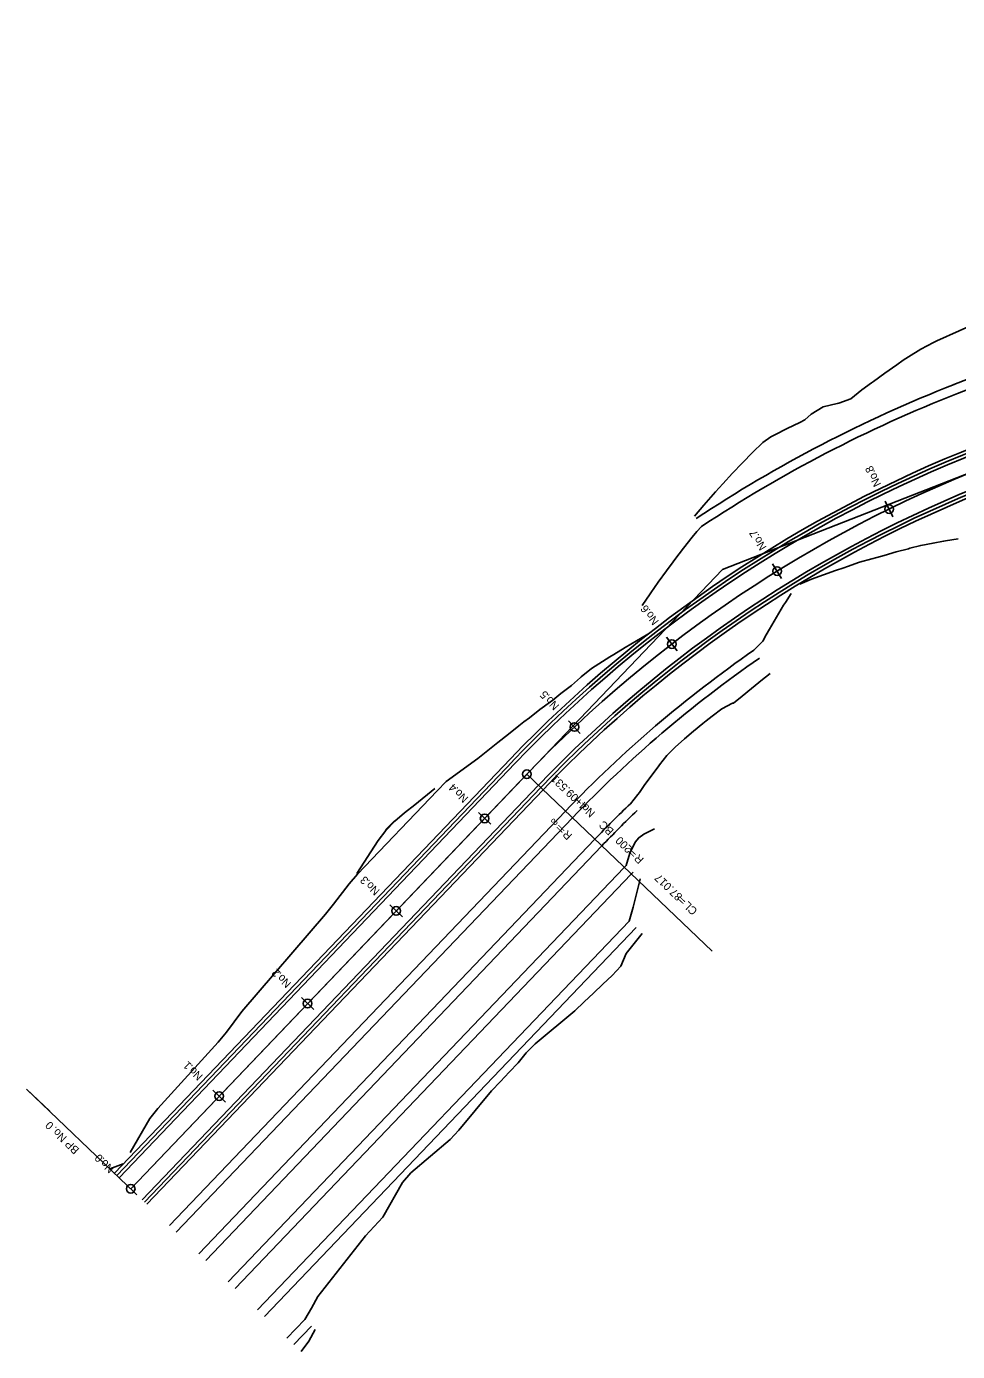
# Model space of a CAD drawing. Extents: x 46571 to 46965, y 10697 to 11034.
# Drawn here: x 46571.1 to 46716.5, y 10697.1 to 10904 of the extents above; entities that cross this region are included whole.
import ezdxf

# ---------------------------------------------------------------- set-up
doc = ezdxf.new("R2010")
doc.units = 0
for name, color, linetype in [('Default', 7, 'Continuous'), ('作業レイヤ1', 7, 'Continuous'), ('地形_主曲線_等高線', 7, 'Continuous'), ('地形_土崖 コンクリート、堅固な石積等斜面（地理院地図Vector）', 7, 'Continuous'), ('建物_普通建物_普通建物（地理院地図Vector）', 7, 'Continuous'), ('建物_普通建物_普通建物（外周線）（地理院地図Vector）', 7, 'Continuous'), ('河川_通常部（地理院地図Vector）', 7, 'Continuous'), ('現況_地形_三角形', 7, 'Continuous'), ('等高線等深線_等高線_主曲線通常部（地理院地図Vector）', 7, 'Continuous'), ('道路_通常部_通常部（地理院地図Vector）', 7, 'Continuous')]:
    doc.layers.add(name, color=color, linetype=linetype)

msp = doc.modelspace()

# ---------------------------------------------------------------- linework, layer by layer
at = {"layer": 'Default'}
for p, q in [((46679.76, 10819.21), (46896.47, 10904.04)), ((46705.79, 10828.67), (46705.79, 10828.67)), ((46587.37, 10722.52), (46679.76, 10819.21)), ((46688.3, 10818.98), (46688.3, 10818.98)), ((46671.86, 10807.59), (46671.86, 10807.59)), ((46656.65, 10794.63), (46656.65, 10794.63)), ((46587.37, 10722.52), (46649.22, 10787.25)), ((46649.22, 10787.25), (46649.22, 10787.25)), ((46649.22, 10787.25), (46678.14, 10759.62)), ((46642.64, 10780.36), (46642.64, 10780.36)), ((46628.82, 10765.9), (46628.82, 10765.9)), ((46615, 10751.44), (46615, 10751.44)), ((46586.88, 10722.98), (46571.1, 10738.06)), ((46571.1, 10738.06), (46574.72, 10734.61)), ((46601.19, 10736.98), (46601.19, 10736.98)), ((46587.37, 10722.52), (46587.37, 10722.52)), ((46587.37, 10722.52), (46587.37, 10722.52))]:
    msp.add_line(p, q, dxfattribs=at)
for centre in [(46705.79, 10828.67), (46688.3, 10818.98), (46671.86, 10807.59), (46656.65, 10794.63), (46649.22, 10787.25), (46642.64, 10780.36), (46628.82, 10765.9), (46615, 10751.44), (46601.19, 10736.98), (46587.37, 10722.52), (46587.37, 10722.52)]:
    msp.add_circle(centre, 0.675, dxfattribs=at)
msp.add_arc((46793.83, 10649.09), 200, 111.3768, 136.3054, dxfattribs=at)
msp.add_arc((46793.83, 10649.09), 200, 111.3768, 136.3054, dxfattribs=at)
at = {"layer": '作業レイヤ1'}
msp.add_line((46587.37, 10722.52), (46649.22, 10787.25), dxfattribs=at)
msp.add_arc((46793.83, 10649.09), 200, 111.3768, 136.3054, dxfattribs=at)
at = {"layer": '地形_主曲線_等高線'}
for p, q in [((46715.92, 10848.11), (46760.11, 10865.41)), ((46716.47, 10846.72), (46760.66, 10864.01)), ((46584.13, 10725.61), (46586.2, 10726.4))]:
    msp.add_line(p, q, dxfattribs=at)
for points in [[(46675.41, 10827.55), (46676.85, 10829.26), (46678.32, 10830.95), (46678.68, 10831.35), (46679.82, 10832.62), (46681.35, 10834.27), (46682.83, 10835.83), (46682.9, 10835.9), (46684.48, 10837.51), (46686.09, 10839.09), (46687.31, 10839.93), (46687.94, 10840.26), (46689.89, 10841.24), (46691.86, 10842.19), (46692.62, 10842.6), (46693.64, 10843.5), (46695.52, 10844.63), (46697.7, 10845.15), (46697.95, 10845.21), (46699.79, 10845.86), (46701.53, 10847.27), (46703.03, 10848.38), (46703.33, 10848.6), (46705.15, 10849.9), (46706.99, 10851.19), (46708.01, 10851.9), (46708.84, 10852.46), (46710.73, 10853.65), (46712.7, 10854.69), (46713.25, 10854.95), (46723.72, 10859.62)], [(46667.24, 10813.6), (46668.47, 10815.42), (46668.57, 10815.57), (46669.73, 10817.23), (46671.01, 10819.01), (46672.06, 10820.43), (46672.33, 10820.79), (46673.67, 10822.54), (46675.04, 10824.28), (46675.76, 10825.17), (46676.49, 10825.93)], [(46691.87, 10816.95), (46693.7, 10817.71), (46695.57, 10818.4), (46697.44, 10819.07), (46698.71, 10819.51), (46699.31, 10819.72), (46701.19, 10820.36), (46703.1, 10820.91), (46703.86, 10821.12), (46705.01, 10821.44), (46706.91, 10821.97), (46708.82, 10822.48), (46709.04, 10822.54), (46710.72, 10822.99), (46712.67, 10823.36), (46714.3, 10823.65), (46714.62, 10823.71), (46716.57, 10824.04)]]:
    msp.add_lwpolyline(points, dxfattribs=at)
for radius in [213.73, 212.23]:
    msp.add_arc((46793.83, 10649.09), radius, 111.3768, 123.5659, dxfattribs=at)
at = {"layer": '地形_土崖 コンクリート、堅固な石積等斜面（地理院地図Vector）'}
for p, q in [((46585.2, 10724.59), (46647.05, 10789.32)), ((46589.54, 10720.44), (46651.39, 10785.18))]:
    msp.add_line(p, q, dxfattribs=at)
for radius in [203, 197]:
    msp.add_arc((46793.83, 10649.09), radius, 111.3768, 136.3054, dxfattribs=at)
at = {"layer": '建物_普通建物_普通建物（地理院地図Vector）'}
for p, q in [((46585.56, 10724.24), (46647.41, 10788.98)), ((46589.18, 10720.79), (46651.03, 10785.52))]:
    msp.add_line(p, q, dxfattribs=at)
for radius in [202.5, 197.5]:
    msp.add_arc((46793.83, 10649.09), radius, 111.3768, 136.3054, dxfattribs=at)
at = {"layer": '建物_普通建物_普通建物（外周線）（地理院地図Vector）'}
for p, q in [((46584.84, 10724.93), (46646.69, 10789.67)), ((46589.9, 10720.1), (46651.75, 10784.83))]:
    msp.add_line(p, q, dxfattribs=at)
for radius in [203.5, 196.5]:
    msp.add_arc((46793.83, 10649.09), radius, 111.3768, 136.3054, dxfattribs=at)
at = {"layer": '現況_地形_三角形'}
for p, q in [((46593.41, 10716.75), (46655.26, 10781.48)), ((46594.49, 10715.71), (46656.34, 10780.45)), ((46627.15, 10778.56), (46628.54, 10780)), ((46598, 10712.36), (46659.85, 10777.09)), ((46599.09, 10711.33), (46660.93, 10776.06)), ((46608.27, 10702.55), (46666.3, 10763.29)), ((46612.86, 10698.17), (46615.62, 10701.06))]:
    msp.add_line(p, q, dxfattribs=at)
for points in [[(46684.69, 10806.63), (46686.07, 10808.02), (46686.6, 10809.01), (46687.11, 10809.92), (46688.19, 10811.8), (46689.31, 10813.65), (46689.59, 10814.09), (46690.48, 10815.47)], [(46587.27, 10728.15), (46590.37, 10733.48), (46591.6, 10735.07), (46601.03, 10745.43), (46602.33, 10746.95), (46603.51, 10748.59), (46604.7, 10750.22), (46617.79, 10765.38), (46619.04, 10766.95), (46621.51, 10770.12), (46622.78, 10771.67), (46635.22, 10784.68), (46636.61, 10786.11), (46641.55, 10789.7), (46643.13, 10790.95), (46644.72, 10792.22), (46646.34, 10793.52), (46647.98, 10794.81), (46648.77, 10795.43), (46649.62, 10796.08), (46651.27, 10797.34), (46652.92, 10798.58), (46653.26, 10798.84), (46654.56, 10799.84), (46656.18, 10801.11), (46657.6, 10802.36), (46657.72, 10802.46), (46659.31, 10803.75), (46661.04, 10804.88), (46662.18, 10805.58), (46662.81, 10805.96), (46664.58, 10807.03), (46666.35, 10808.08), (46666.99, 10808.46), (46668.12, 10809.12)], [(46665.39, 10782.65), (46666.58, 10784.09), (46666.8, 10784.41), (46667.67, 10785.64), (46668.79, 10787.18), (46669.84, 10788.58), (46669.93, 10788.7), (46671.1, 10790.2), (46672.42, 10791.53), (46673.32, 10792.33), (46673.83, 10792.76), (46675.26, 10793.97), (46676.71, 10795.16), (46677.23, 10795.58), (46678.17, 10796.33), (46679.66, 10797.47), (46681.34, 10798.34), (46681.51, 10798.37), (46682.86, 10799.43), (46684.28, 10800.65), (46685.45, 10801.59), (46685.75, 10801.82), (46687.21, 10802.99)], [(46622.7, 10771.74), (46625.99, 10776.9), (46627.23, 10778.49), (46628.61, 10779.93), (46630.13, 10781.25), (46631.72, 10782.49), (46634.84, 10785.04)], [(46602.59, 10707.97), (46664.44, 10772.71), (46664.73, 10773.01), (46665.32, 10774.94), (46666.16, 10776.64), (46666.7, 10777.34), (46667.47, 10777.89), (46669.16, 10778.73)], [(46603.68, 10706.94), (46665.53, 10771.67), (46665.81, 10771.97)], [(46607.18, 10703.59), (46665.21, 10764.32), (46665.82, 10766.5), (46666.82, 10770.43), (46666.93, 10770.9)], [(46611.77, 10699.2), (46614.54, 10702.09), (46615.6, 10703.85), (46616.6, 10705.66), (46624.03, 10715.15), (46625.37, 10716.64), (46626.74, 10718.09), (46629.79, 10723.48), (46631.1, 10724.99), (46637.26, 10730.18), (46638.61, 10731.65), (46643.72, 10737.83), (46645.1, 10739.28), (46646.47, 10740.73), (46647.85, 10742.19), (46649.14, 10743.72), (46650.51, 10745.17), (46656.71, 10750.31), (46658.16, 10751.7), (46659.61, 10753.08), (46661.07, 10754.45), (46662.53, 10755.82), (46663.92, 10757.26), (46664.74, 10759.24), (46667.24, 10762.39)], [(46613.98, 10697.09), (46615.18, 10698.72), (46616.16, 10700.54)]]:
    msp.add_lwpolyline(points, dxfattribs=at)
for radius, start in [(191.65, 124.7118), (190.15, 124.7118), (185.3, 133.8791), (183.8, 133.8791)]:
    msp.add_arc((46793.83, 10649.09), radius, start, 136.3054, dxfattribs=at)
at = {"layer": '等高線等深線_等高線_主曲線通常部（地理院地図Vector）'}
msp.add_line((46587.37, 10722.52), (46649.22, 10787.25), dxfattribs=at)
msp.add_arc((46793.83, 10649.09), 200, 111.3768, 136.3054, dxfattribs=at)
at = {"layer": '道路_通常部_通常部（地理院地図Vector）'}
for p, q in [((46705.19, 10829.88), (46706.38, 10827.45)), ((46687.58, 10820.13), (46689.01, 10817.83)), ((46671.04, 10808.66), (46672.69, 10806.53)), ((46655.72, 10795.61), (46657.57, 10793.64)), ((46641.66, 10781.29), (46643.61, 10779.43)), ((46627.84, 10766.83), (46629.8, 10764.97)), ((46614.03, 10752.37), (46615.98, 10750.51)), ((46600.21, 10737.91), (46602.16, 10736.04)), ((46586.4, 10723.45), (46588.35, 10721.58))]:
    msp.add_line(p, q, dxfattribs=at)

# ---------------------------------------------------------------- texts
at = {"layer": 'Default'}
for s, p in [('4+09.531', (46658.79, 10782.43)), ('BC\u3000No.', (46662.9, 10778.5)), ('R＝∞', (46656.42, 10777.78)), ('200', (46665.82, 10775.71)), ('R＝', (46667.58, 10774.03)), ('87.017', (46673.62, 10768.26)), ('CL＝', (46675.97, 10766.02)), ('0', (46575.44, 10732.51)), ('BP No.', (46579.44, 10728.69))]:
    msp.add_text(s, height=1.25, rotation=136.3054, dxfattribs=at).set_placement(p)
at = {"layer": '河川_通常部（地理院地図Vector）'}
for s, rotation, p in [('8', 116.1174, (46703.51, 10834.72)), ('No.', 116.1174, (46704.59, 10832.53)), ('7', 121.847, (46685.43, 10824.78)), ('No.', 121.847, (46686.72, 10822.71)), ('6', 127.5766, (46668.43, 10813.08)), ('No.', 127.5766, (46669.92, 10811.15)), ('5', 133.3061, (46652.69, 10799.74)), ('No.', 133.3061, (46654.36, 10797.97)), ('4', 136.3054, (46638.42, 10785.26)), ('No.', 136.3054, (46640.18, 10783.57)), ('3', 136.3054, (46624.6, 10770.8)), ('No.', 136.3054, (46626.36, 10769.11)), ('2', 136.3054, (46610.78, 10756.34)), ('No.', 136.3054, (46612.54, 10754.65)), ('1', 136.3054, (46596.97, 10741.88)), ('No.', 136.3054, (46598.73, 10740.19)), ('0', 136.3054, (46583.15, 10727.41)), ('No.', 136.3054, (46584.91, 10725.73))]:
    msp.add_text(s, height=1.25, rotation=rotation, dxfattribs=at).set_placement(p)

doc.saveas('drawing.dxf')
